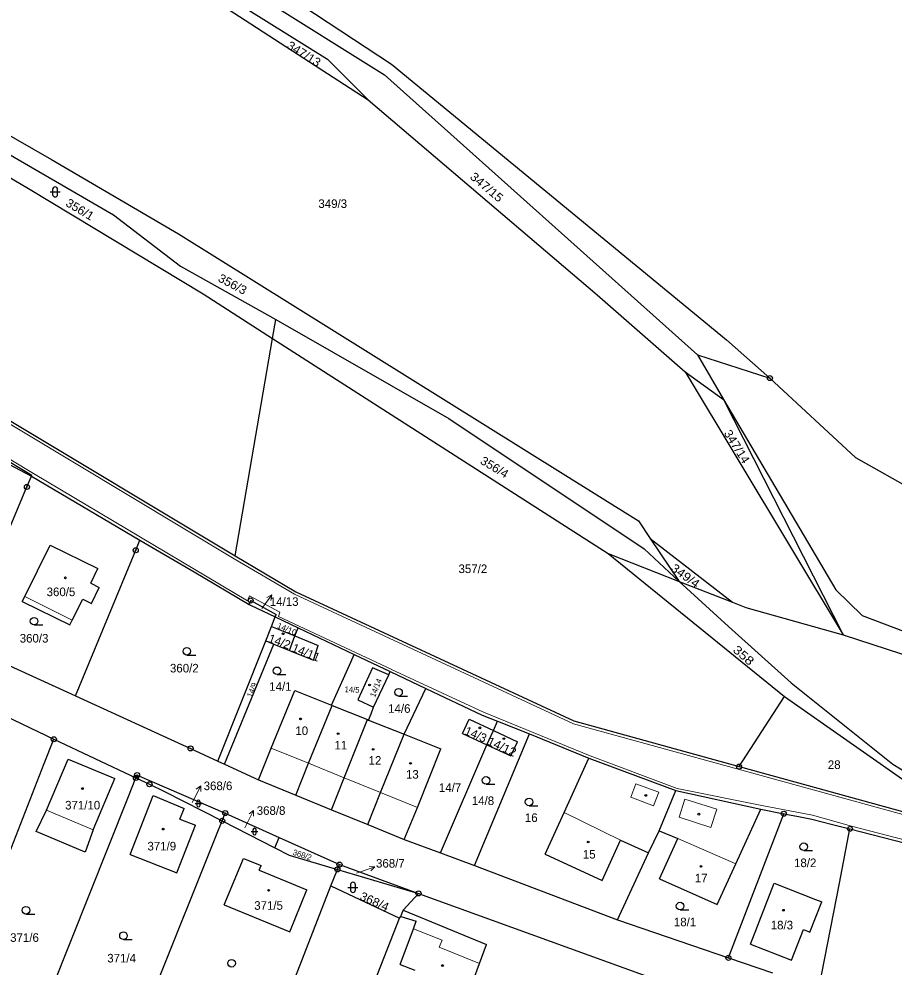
# Model space of a CAD drawing. Extents: x -633485 to -630509, y -1112692 to -1108818.
# Drawn here: x -632263.7 to -632090.4, y -1111838.6 to -1111650.8 of the extents above; entities that cross this region are included whole.
import ezdxf
from ezdxf.enums import TextEntityAlignment as Align

# ---------------------------------------------------------------- set-up
doc = ezdxf.new("R2010")
doc.units = 0
doc.header["$LTSCALE"] = 0.68
for name, color, linetype, lineweight in [('1', 7, 'Continuous', 25), ('3', 7, 'Continuous', 25), ('4', 7, 'Continuous', 13), ('5', 7, 'Continuous', 25), ('7', 7, 'Continuous', 13), ('8', 7, 'Continuous', 25)]:
    doc.layers.add(name, color=color, linetype=linetype, lineweight=lineweight)
doc.layers.add('2', color=7, linetype='Continuous')

msp = doc.modelspace()

# ---------------------------------------------------------------- linework, layer by layer
at = {"layer": '1'}
for p, q in [((-632259.96, -1111613.75), (-632189.94, -1111659.79)), ((-632258.45, -1111619.96), (-632191.31, -1111661.88)), ((-632261.9, -1111621.78), (-632202.65, -1111658.82)), ((-632261.22, -1111623.63), (-632194.6, -1111666.89)), ((-632326.93, -1111645.87), (-632261.86, -1111684.44)), ((-632296.31, -1111656.36), (-632257.3, -1111678.64)), ((-632202.65, -1111658.82), (-632194.6, -1111666.89)), ((-632189.94, -1111659.79), (-632123.57, -1111714.39)), ((-632293.52, -1111661.47), (-632245.01, -1111689.64)), ((-632191.31, -1111661.88), (-632129.37, -1111717.35)), ((-632194.6, -1111666.89), (-632149.21, -1111705.45)), ((-632257.3, -1111678.64), (-632232.16, -1111693.36)), ((-632261.86, -1111684.44), (-632227.27, -1111705.26)), ((-632245.01, -1111689.64), (-632231.75, -1111699.8)), ((-632325.73, -1111694.38), (-632220.93, -1111757.12)), ((-632232.16, -1111693.36), (-632141.06, -1111750.24)), ((-632231.75, -1111699.8), (-632212.85, -1111710.33)), ((-632227.27, -1111705.26), (-632213.5, -1111714.09)), ((-632149.21, -1111705.45), (-632131.81, -1111720.71)), ((-632213.5, -1111714.09), (-632212.85, -1111710.33)), ((-632212.85, -1111710.33), (-632178.58, -1111729.95)), ((-632220.93, -1111757.12), (-632213.5, -1111714.09)), ((-632213.5, -1111714.09), (-632147.05, -1111756.7)), ((-632123.57, -1111714.39), (-632115, -1111721.96)), ((-632129.37, -1111717.35), (-632115, -1111721.96)), ((-632129.37, -1111717.35), (-632124.17, -1111726.18)), ((-632131.81, -1111720.71), (-632124.17, -1111726.18)), ((-632131.81, -1111720.71), (-632100.47, -1111772.77)), ((-632115, -1111721.96), (-632098.05, -1111737.68)), ((-632124.17, -1111726.18), (-632100.47, -1111772.77)), ((-632124.17, -1111726.18), (-632101.97, -1111763.89)), ((-632288.65, -1111726.87), (-632261.27, -1111741.38)), ((-632178.58, -1111729.95), (-632139.91, -1111755.75)), ((-632274.31, -1111733.41), (-632261.17, -1111741.15)), ((-632098.05, -1111737.68), (-632078.38, -1111748.73)), ((-632262.16, -1111743.5), (-632261.27, -1111741.38)), ((-632261.27, -1111741.38), (-632261.17, -1111741.15)), ((-632261.27, -1111741.38), (-632239.78, -1111754.03)), ((-632275.15, -1111774.29), (-632262.16, -1111743.5)), ((-632141.06, -1111750.24), (-632138.7, -1111753.74)), ((-632240.61, -1111756.04), (-632239.78, -1111754.03)), ((-632239.78, -1111754.03), (-632229.03, -1111760.31)), ((-632138.7, -1111753.74), (-632122.42, -1111766.32)), ((-632138.7, -1111753.74), (-632132.97, -1111762.22)), ((-632262.61, -1111765.21), (-632257.55, -1111755)), ((-632257.55, -1111755), (-632248.1, -1111759.68)), ((-632252.52, -1111784.87), (-632240.61, -1111756.04)), ((-632139.91, -1111755.75), (-632132.97, -1111762.22)), ((-632220.93, -1111757.12), (-632208.93, -1111764.3)), ((-632147.05, -1111756.7), (-632112.13, -1111784.99)), ((-632147.05, -1111756.7), (-632132.97, -1111762.22)), ((-632249.53, -1111762.57), (-632248.1, -1111759.68)), ((-632229.03, -1111760.31), (-632218.16, -1111766.76)), ((-632249.53, -1111762.57), (-632247.84, -1111763.4)), ((-632249.39, -1111766.58), (-632247.84, -1111763.4)), ((-632132.97, -1111762.22), (-632123.19, -1111771.16)), ((-632132.97, -1111762.22), (-632122.42, -1111766.32)), ((-632101.97, -1111763.89), (-632096.75, -1111768.94)), ((-632263.08, -1111766.16), (-632262.61, -1111765.21)), ((-632253.18, -1111769.89), (-632251.1, -1111765.73)), ((-632251.1, -1111765.73), (-632249.39, -1111766.58)), ((-632208.93, -1111764.3), (-632153.83, -1111789.82)), ((-632263.08, -1111766.16), (-632253.64, -1111770.81)), ((-632218.16, -1111766.76), (-632217.85, -1111765.99)), ((-632218.16, -1111766.76), (-632217.86, -1111766.94)), ((-632217.86, -1111766.94), (-632212.98, -1111769.25)), ((-632217.85, -1111765.99), (-632212.78, -1111768.74)), ((-632122.42, -1111766.32), (-632119.76, -1111767.35)), ((-632119.76, -1111767.35), (-632100.47, -1111772.77)), ((-632213.72, -1111771.11), (-632212.98, -1111769.25)), ((-632212.98, -1111769.25), (-632212.78, -1111768.74)), ((-632212.98, -1111769.25), (-632208.44, -1111771.4)), ((-632096.75, -1111768.94), (-632068.27, -1111779.85)), ((-632253.64, -1111770.81), (-632253.18, -1111769.89)), ((-632214.87, -1111773.99), (-632213.72, -1111771.11)), ((-632213.72, -1111771.11), (-632209.1, -1111773.01)), ((-632209.1, -1111773.01), (-632208.44, -1111771.4)), ((-632208.44, -1111771.4), (-632197.32, -1111776.68)), ((-632123.19, -1111771.16), (-632110.8, -1111782.31)), ((-632210.14, -1111775.88), (-632209.1, -1111773.01)), ((-632209.1, -1111773.01), (-632204.47, -1111774.91)), ((-632100.47, -1111772.77), (-632053.61, -1111788.03)), ((-632275.23, -1111774.49), (-632252.52, -1111784.87)), ((-632224.35, -1111797.78), (-632214.87, -1111773.99)), ((-632223.06, -1111798.38), (-632213.28, -1111774.62)), ((-632214.87, -1111773.99), (-632213.28, -1111774.62)), ((-632213.28, -1111774.62), (-632210.14, -1111775.88)), ((-632205.4, -1111777.77), (-632204.47, -1111774.91)), ((-632210.14, -1111775.88), (-632205.4, -1111777.77)), ((-632198.01, -1111778.2), (-632197.32, -1111776.68)), ((-632197.32, -1111776.68), (-632190.2, -1111780.05)), ((-632201.87, -1111786.7), (-632198.01, -1111778.2)), ((-632193.75, -1111779.3), (-632196.63, -1111785.65)), ((-632190.51, -1111780.71), (-632193.75, -1111779.3)), ((-632193.55, -1111787.13), (-632190.51, -1111780.71)), ((-632190.51, -1111780.71), (-632190.2, -1111780.05)), ((-632190.2, -1111780.05), (-632183.18, -1111783.39)), ((-632279.29, -1111782.74), (-632256.84, -1111793.46)), ((-632110.8, -1111782.31), (-632090.65, -1111798.4)), ((-632213.82, -1111795.21), (-632209.12, -1111783.8)), ((-632209.12, -1111783.8), (-632201.87, -1111786.7)), ((-632187.47, -1111792.47), (-632183.18, -1111783.39)), ((-632183.18, -1111783.39), (-632172, -1111788.69)), ((-632252.52, -1111784.87), (-632229.74, -1111795.28)), ((-632196.63, -1111785.65), (-632193.55, -1111787.13)), ((-632121.12, -1111798.87), (-632112.13, -1111784.99)), ((-632112.13, -1111784.99), (-632073.84, -1111811.83)), ((-632206.38, -1111798.22), (-632201.7, -1111786.77)), ((-632201.87, -1111786.7), (-632201.7, -1111786.77)), ((-632201.7, -1111786.77), (-632194.68, -1111789.58)), ((-632194.5, -1111789.65), (-632193.99, -1111788.4)), ((-632193.99, -1111788.4), (-632193.55, -1111787.13)), ((-632199.34, -1111801.07), (-632194.68, -1111789.58)), ((-632194.68, -1111789.58), (-632194.5, -1111789.65)), ((-632194.5, -1111789.65), (-632187.47, -1111792.47)), ((-632175.86, -1111792.33), (-632174.55, -1111789.5)), ((-632174.55, -1111789.5), (-632169.78, -1111791.72)), ((-632172, -1111788.69), (-632168.93, -1111789.89)), ((-632169.78, -1111791.72), (-632168.93, -1111789.89)), ((-632168.93, -1111789.89), (-632162.6, -1111792.36)), ((-632153.83, -1111789.82), (-632121.12, -1111798.87)), ((-632171.09, -1111794.54), (-632169.78, -1111791.72)), ((-632169.78, -1111791.72), (-632165.01, -1111793.95)), ((-632258.76, -1111798.26), (-632256.84, -1111793.46)), ((-632256.84, -1111793.46), (-632240.57, -1111801.11)), ((-632192.11, -1111803.99), (-632187.47, -1111792.47)), ((-632187.47, -1111792.47), (-632180.19, -1111795.38)), ((-632175.86, -1111792.33), (-632171.09, -1111794.54)), ((-632173.54, -1111818.43), (-632162.6, -1111792.36)), ((-632166.32, -1111796.76), (-632165.01, -1111793.95)), ((-632162.6, -1111792.36), (-632150.88, -1111797.21)), ((-632229.74, -1111795.28), (-632224.35, -1111797.78)), ((-632216.3, -1111801.52), (-632213.82, -1111795.21)), ((-632184.82, -1111806.94), (-632180.19, -1111795.38)), ((-632180.26, -1111815.96), (-632171.09, -1111794.54)), ((-632171.09, -1111794.54), (-632166.32, -1111796.76)), ((-632258.27, -1111807.53), (-632253.99, -1111797.37)), ((-632253.99, -1111797.37), (-632244.76, -1111801.22)), ((-632224.35, -1111797.78), (-632223.06, -1111798.38)), ((-632155.77, -1111807.99), (-632150.88, -1111797.21)), ((-632150.88, -1111797.21), (-632133.61, -1111803.63)), ((-632283.16, -1111860.74), (-632258.76, -1111798.26)), ((-632223.06, -1111798.38), (-632216.3, -1111801.52)), ((-632208.88, -1111804.55), (-632206.38, -1111798.22)), ((-632121.12, -1111798.87), (-632073.84, -1111811.83)), ((-632090.65, -1111798.4), (-632083.46, -1111802.85)), ((-632249.03, -1111811.42), (-632244.76, -1111801.22)), ((-632242.18, -1111805.12), (-632240.57, -1111801.11)), ((-632240.57, -1111801.11), (-632240.35, -1111800.56)), ((-632240.57, -1111801.11), (-632237.89, -1111802.38)), ((-632240.35, -1111800.56), (-632222.88, -1111808.08)), ((-632216.3, -1111801.52), (-632208.88, -1111804.55)), ((-632201.86, -1111807.42), (-632199.34, -1111801.07)), ((-632237.89, -1111802.38), (-632234.91, -1111803.78)), ((-632264.78, -1111861.71), (-632242.18, -1111805.12)), ((-632241.69, -1111816.26), (-632237.13, -1111804.6)), ((-632237.13, -1111804.6), (-632231.03, -1111807.2)), ((-632234.91, -1111803.78), (-632223.49, -1111809.61)), ((-632208.88, -1111804.55), (-632201.86, -1111807.42)), ((-632194.66, -1111810.37), (-632192.11, -1111803.99)), ((-632136.94, -1111811.57), (-632133.61, -1111803.63)), ((-632133.61, -1111803.63), (-632116.83, -1111807.3)), ((-632187.42, -1111813.33), (-632184.82, -1111806.94)), ((-632260.32, -1111811.75), (-632258.27, -1111807.53)), ((-632231.87, -1111809.27), (-632231.03, -1111807.2)), ((-632223.49, -1111809.61), (-632222.88, -1111808.08)), ((-632222.88, -1111808.08), (-632212.18, -1111812.9)), ((-632201.86, -1111807.42), (-632194.66, -1111810.37)), ((-632159.55, -1111816.18), (-632155.77, -1111807.99)), ((-632122.95, -1111836.03), (-632112.25, -1111808.2)), ((-632121.78, -1111818.14), (-632116.83, -1111807.3)), ((-632116.83, -1111807.3), (-632112.25, -1111808.2)), ((-632112.25, -1111808.2), (-632109.65, -1111808.66)), ((-632109.65, -1111808.66), (-632106.72, -1111809.28)), ((-632232.46, -1111819.89), (-632228.76, -1111810.48)), ((-632231.87, -1111809.27), (-632228.76, -1111810.48)), ((-632224.61, -1111812.39), (-632223.49, -1111809.61)), ((-632223.49, -1111809.61), (-632213.05, -1111814.95)), ((-632194.66, -1111810.37), (-632187.42, -1111813.33)), ((-632106.72, -1111809.28), (-632102.61, -1111810.33)), ((-632102.61, -1111810.33), (-632099.14, -1111811.2)), ((-632244.86, -1111862.76), (-632224.61, -1111812.39)), ((-632139.04, -1111815.92), (-632136.94, -1111811.57)), ((-632136.94, -1111811.57), (-632133.22, -1111813.13)), ((-632101.24, -1111821.96), (-632099.14, -1111811.2)), ((-632099.14, -1111811.2), (-632071.85, -1111818.23)), ((-632213.05, -1111814.95), (-632212.18, -1111812.9)), ((-632212.18, -1111812.9), (-632200.26, -1111818.27)), ((-632187.42, -1111813.33), (-632180.26, -1111815.96)), ((-632148.21, -1111821.42), (-632144.59, -1111813.45)), ((-632144.59, -1111813.45), (-632139.04, -1111815.92)), ((-632136.88, -1111821.08), (-632133.22, -1111813.13)), ((-632241.69, -1111816.26), (-632232.46, -1111819.89)), ((-632213.05, -1111814.95), (-632210.23, -1111816.39)), ((-632210.23, -1111816.39), (-632200.67, -1111819.22)), ((-632180.26, -1111815.96), (-632173.54, -1111818.43)), ((-632159.55, -1111816.18), (-632148.21, -1111821.42)), ((-632145.21, -1111829.21), (-632139.04, -1111815.92)), ((-632223.12, -1111826.27), (-632219.26, -1111817.05)), ((-632219.26, -1111817.05), (-632215.75, -1111818.48)), ((-632200.67, -1111819.22), (-632200.26, -1111818.27)), ((-632200.26, -1111818.27), (-632184.61, -1111823.98)), ((-632173.54, -1111818.43), (-632145.21, -1111829.21)), ((-632125.43, -1111826.15), (-632121.78, -1111818.14)), ((-632216.17, -1111819.38), (-632215.75, -1111818.48)), ((-632216.17, -1111819.38), (-632206.7, -1111823.25)), ((-632201.95, -1111822.48), (-632200.67, -1111819.22)), ((-632200.67, -1111819.22), (-632184.61, -1111823.98)), ((-632136.88, -1111821.08), (-632125.43, -1111826.15)), ((-632118.86, -1111834.05), (-632114.19, -1111821.98)), ((-632114.19, -1111821.98), (-632106, -1111825.17)), ((-632105.33, -1111843.03), (-632101.24, -1111821.96)), ((-632217.08, -1111861.1), (-632201.95, -1111822.48)), ((-632210.12, -1111831.6), (-632206.7, -1111823.25)), ((-632201.95, -1111822.48), (-632188.36, -1111828.9)), ((-632187.62, -1111827.29), (-632184.61, -1111823.98)), ((-632184.61, -1111823.98), (-632129.27, -1111844)), ((-632107.07, -1111831.65), (-632104.74, -1111825.67)), ((-632106, -1111825.17), (-632104.74, -1111825.67)), ((-632223.12, -1111826.27), (-632210.12, -1111831.6)), ((-632188.11, -1111828.54), (-632187.62, -1111827.29)), ((-632187.62, -1111827.29), (-632171.17, -1111834.07)), ((-632198.55, -1111854.72), (-632188.36, -1111828.9)), ((-632188.36, -1111828.9), (-632188.11, -1111828.54)), ((-632188.11, -1111828.54), (-632185.1, -1111829.5)), ((-632185.59, -1111830.98), (-632185.1, -1111829.5)), ((-632145.21, -1111829.21), (-632123.23, -1111836.74)), ((-632188.27, -1111838.03), (-632185.59, -1111830.98)), ((-632110.72, -1111837.19), (-632108.36, -1111831.15)), ((-632108.36, -1111831.15), (-632107.07, -1111831.65)), ((-632172.54, -1111837.85), (-632171.17, -1111834.07)), ((-632118.86, -1111834.05), (-632110.72, -1111837.19)), ((-632123.23, -1111836.74), (-632122.95, -1111836.03)), ((-632123.23, -1111836.74), (-632114.46, -1111839.74)), ((-632188.27, -1111838.03), (-632185.32, -1111839.15)), ((-632175.75, -1111846.71), (-632172.54, -1111837.85))]:
    msp.add_line(p, q, dxfattribs=at)
msp.add_lwpolyline([(-632249.03, -1111811.42), (-632250.62, -1111815.82), (-632260.32, -1111811.75)], dxfattribs=at)
at = {"layer": '3'}
for p, q in [((-632257.581, -1111685.091), (-632255.579, -1111685.091)), ((-632257.081, -1111684.591), (-632257.081, -1111685.592)), ((-632256.079, -1111685.592), (-632256.079, -1111684.591)), ((-632260.753, -1111770.83), (-632259.003, -1111770.83)), ((-632230.493, -1111776.78), (-632228.743, -1111776.78)), ((-632212.623, -1111780.66), (-632210.873, -1111780.66)), ((-632188.563, -1111784.9), (-632186.813, -1111784.9)), ((-632171.223, -1111802.35), (-632169.473, -1111802.35)), ((-632228.861, -1111806.191), (-632227.519, -1111806.191)), ((-632228.525, -1111805.855), (-632228.525, -1111806.526)), ((-632227.855, -1111806.526), (-632227.855, -1111805.855)), ((-632162.713, -1111806.63), (-632160.963, -1111806.63)), ((-632217.741, -1111811.741), (-632216.399, -1111811.741)), ((-632217.405, -1111811.405), (-632217.405, -1111812.076)), ((-632216.735, -1111812.076), (-632216.735, -1111811.405)), ((-632108.313, -1111815.5), (-632106.563, -1111815.5)), ((-632198.601, -1111822.781), (-632196.599, -1111822.781)), ((-632198.101, -1111822.281), (-632198.101, -1111823.282)), ((-632197.099, -1111823.282), (-632197.099, -1111822.281)), ((-632132.793, -1111827.24), (-632131.043, -1111827.24)), ((-632262.353, -1111828.08), (-632260.603, -1111828.08)), ((-632243.043, -1111833.1), (-632241.293, -1111833.1))]:
    msp.add_line(p, q, dxfattribs=at)
for centre in [(-632260.7529, -1111770.0798), (-632230.4929, -1111776.0298), (-632212.6229, -1111779.9098), (-632188.5629, -1111784.1498), (-632171.2229, -1111801.5998), (-632162.7129, -1111805.8798), (-632108.3129, -1111814.7498), (-632132.7929, -1111826.4898), (-632262.3529, -1111827.3298), (-632243.0429, -1111832.3498), (-632221.6229, -1111837.8098)]:
    msp.add_circle(centre, 0.75, dxfattribs=at)
for centre, radius, start, end in [((-632256.58, -1111684.5909), 0.5, 0, 180), ((-632256.58, -1111685.5909), 0.5, 180, 359.98789), ((-632228.19, -1111805.8556), 0.335, 0, 180), ((-632228.19, -1111806.5256), 0.335, 180, 359.98789), ((-632217.07, -1111811.4056), 0.335, 0, 180), ((-632217.07, -1111812.0756), 0.335, 180, 359.98789), ((-632197.6, -1111822.2809), 0.5, 0, 180), ((-632197.6, -1111823.2809), 0.5, 180, 359.98789)]:
    msp.add_arc(centre, radius, start, end, dxfattribs=at)
at = {"layer": '4'}
for p, q in [((-632262.61, -1111765.21), (-632253.18, -1111769.89)), ((-632213.82, -1111795.21), (-632206.38, -1111798.22)), ((-632206.38, -1111798.22), (-632199.34, -1111801.07)), ((-632199.34, -1111801.07), (-632192.11, -1111803.99)), ((-632142.55, -1111804.94), (-632141.56, -1111802.26)), ((-632141.56, -1111802.26), (-632137.03, -1111803.94)), ((-632192.11, -1111803.99), (-632184.82, -1111806.94)), ((-632142.55, -1111804.94), (-632138.04, -1111806.62)), ((-632138.04, -1111806.62), (-632137.03, -1111803.94)), ((-632132.96, -1111808.88), (-632131.88, -1111805.34)), ((-632131.88, -1111805.34), (-632125.54, -1111807.31)), ((-632249.03, -1111811.42), (-632258.27, -1111807.53)), ((-632155.77, -1111807.99), (-632144.59, -1111813.45)), ((-632132.96, -1111808.88), (-632126.72, -1111810.92)), ((-632126.72, -1111810.92), (-632125.54, -1111807.31)), ((-632133.22, -1111813.13), (-632121.78, -1111818.14)), ((-632185.59, -1111830.98), (-632179.95, -1111833.27)), ((-632180.49, -1111834.62), (-632179.95, -1111833.27)), ((-632180.49, -1111834.62), (-632172.54, -1111837.85))]:
    msp.add_line(p, q, dxfattribs=at)
for points in [[(-632121.32, -1111799.36), (-632153.88, -1111790.41), (-632209.17, -1111764.74), (-632221.14, -1111757.71), (-632325.85, -1111694.81), (-632333.76, -1111689.52), (-632341.95, -1111683.42)], [(-632299.24, -1111719.8), (-632274.04, -1111732.92), (-632260.85, -1111740.83), (-632218.48, -1111766.08), (-632218.07, -1111765.09), (-632212.08, -1111768.29), (-632212.31, -1111769.16), (-632189.88, -1111779.63)], [(-632189.94, -1111779.63), (-632171.73, -1111788.1), (-632150.63, -1111796.76), (-632133.35, -1111803.2), (-632116.61, -1111806.57), (-632106.56, -1111808.49), (-632098.83, -1111810.64), (-632072.34, -1111817.55), (-632072.75, -1111816.1), (-632062.98, -1111814.99), (-632051.99, -1111812.26), (-632052.29, -1111810.51)], [(-632052.29, -1111810.51), (-632036.9, -1111809.18), (-632037.48, -1111804), (-632062.36, -1111810.51), (-632070.38, -1111811.56), (-632073.81, -1111812.43), (-632121.32, -1111799.36)]]:
    msp.add_lwpolyline(points, dxfattribs=at)
at = {"layer": '5'}
for centre in [(-632254.5568, -1111761.4992), (-632211.4168, -1111772.5692), (-632194.2935, -1111782.7159), (-632207.9568, -1111789.4392), (-632172.4468, -1111791.1892), (-632200.5368, -1111792.3592), (-632167.6868, -1111793.3392), (-632193.6068, -1111795.4592), (-632186.1968, -1111798.2292), (-632251.1768, -1111803.2292), (-632139.5868, -1111804.5792), (-632129.0868, -1111808.2992), (-632235.1668, -1111811.2392), (-632150.9868, -1111813.7992), (-632128.6468, -1111818.6292), (-632214.2868, -1111823.3692), (-632112.3268, -1111827.3192), (-632179.8468, -1111838.2792)]:
    msp.add_circle(centre, 0.175, dxfattribs=at)
at = {"layer": '7'}
for p, q in [((-632213.676, -1111764.882), (-632214.67, -1111765.398)), ((-632227.718, -1111802.686), (-632228.618, -1111803.351)), ((-632217.278, -1111807.546), (-632218.178, -1111808.211)), ((-632193.283, -1111818.713), (-632194.392, -1111818.566))]:
    msp.add_line(p, q, dxfattribs=at)
for points in [[(-632215.63, -1111767.57), (-632215.44, -1111767.31), (-632213.676, -1111764.882), (-632213.86, -1111765.987)], [(-632229.41, -1111806), (-632229.08, -1111805.36), (-632227.718, -1111802.686), (-632227.726, -1111803.806)], [(-632219.02, -1111810.98), (-632218.64, -1111810.22), (-632217.278, -1111807.546), (-632217.286, -1111808.666)], [(-632196.9, -1111819.97), (-632196.12, -1111819.69), (-632193.283, -1111818.713), (-632194.066, -1111819.512)]]:
    msp.add_lwpolyline(points, dxfattribs=at)
at = {"layer": '8'}
for centre, radius in [((-632115, -1111721.9599), 0.5), ((-632115, -1111721.9599), 0.0303), ((-632262.16, -1111743.4999), 0.5), ((-632262.16, -1111743.4999), 0.0303), ((-632240.61, -1111756.0399), 0.5), ((-632240.61, -1111756.0399), 0.0303), ((-632217.85, -1111765.9899), 0.5), ((-632217.85, -1111765.9899), 0.0303), ((-632256.84, -1111793.4599), 0.5), ((-632256.84, -1111793.4599), 0.0303), ((-632229.74, -1111795.2799), 0.5), ((-632229.74, -1111795.2799), 0.0303), ((-632121.12, -1111798.8699), 0.5), ((-632121.12, -1111798.8699), 0.0303), ((-632240.57, -1111801.1099), 0.5), ((-632240.35, -1111800.5599), 0.5), ((-632240.57, -1111801.1099), 0.0303), ((-632240.35, -1111800.5599), 0.0303), ((-632237.89, -1111802.3799), 0.5), ((-632237.89, -1111802.3799), 0.0303), ((-632222.88, -1111808.0799), 0.5), ((-632222.88, -1111808.0799), 0.0303), ((-632112.25, -1111808.1999), 0.5), ((-632112.25, -1111808.1999), 0.0303), ((-632223.49, -1111809.6099), 0.5), ((-632223.49, -1111809.6099), 0.0303), ((-632099.14, -1111811.1999), 0.5), ((-632099.14, -1111811.1999), 0.0303), ((-632200.26, -1111818.2699), 0.5), ((-632200.26, -1111818.2699), 0.0303), ((-632200.67, -1111819.2199), 0.5), ((-632200.67, -1111819.2199), 0.0303), ((-632184.61, -1111823.9799), 0.5), ((-632184.61, -1111823.9799), 0.0303), ((-632123.23, -1111836.7399), 0.5), ((-632123.23, -1111836.7399), 0.0303)]:
    msp.add_circle(centre, radius, dxfattribs=at)

# ---------------------------------------------------------------- texts
at = {"layer": '2'}
for s, height, rotation, width, p in [('347/13', 1.7, 328, 1.05, (-632210.835, -1111656.54)), ('347/15', 1.7, 320, 1.1, (-632174.563, -1111682.335)), ('356/1', 1.7, 329, 1.05, (-632254.658, -1111687.744)), ('356/3', 1.7, 332, 1.05, (-632224.469, -1111702.695)), ('347/14', 1.7, 302, 1.05, (-632124.2, -1111732.865)), ('356/4', 1.7, 329, 1.05, (-632172.548, -1111738.784)), ('349/4', 1.7, 324, 1.1, (-632134.769, -1111759.943)), ('14/10', 1.139, 337, 1.05, (-632212.751, -1111771.382)), ('358', 1.7, 319, 1.2, (-632122.488, -1111776)), ('368/4', 1.7, 336, 1.05, (-632196.392, -1111825.148))]:
    msp.add_text(s, height=height, rotation=rotation, dxfattribs=dict(at, width=width)).set_placement(p)
for s, p in [('349/3', (-632204.44, -1111688.265)), ('357/2', (-632176.68, -1111760.555)), ('360/5', (-632258.27, -1111765.125)), ('360/3', (-632263.6, -1111774.315)), ('360/2', (-632233.84, -1111780.235)), ('14/1', (-632214.17, -1111783.865)), ('14/6', (-632190.62, -1111788.225)), ('10', (-632209, -1111792.625)), ('11', (-632201.26, -1111795.475)), ('12', (-632194.5, -1111798.495)), ('28', (-632103.53, -1111799.345)), ('13', (-632187.09, -1111801.265)), ('14/7', (-632180.57, -1111803.875)), ('14/8', (-632174.05, -1111806.485)), ('371/10', (-632254.61, -1111807.365)), ('16', (-632163.54, -1111809.835)), ('371/9', (-632238.3, -1111815.475)), ('15', (-632152.05, -1111817.075)), ('18/2', (-632110.23, -1111818.775)), ('17', (-632129.89, -1111821.805)), ('371/5', (-632217.15, -1111827.225)), ('18/1', (-632134.02, -1111830.485)), ('18/3', (-632114.84, -1111831.105)), ('371/6', (-632265.49, -1111833.575)), ('371/4', (-632246.26, -1111837.655))]:
    msp.add_text(s, height=1.7, dxfattribs=at).set_placement(p)
for s, p in [('14/13', (-632211.21, -1111767.055)), ('368/6', (-632224.32, -1111803.535)), ('368/8', (-632213.81, -1111808.425)), ('368/7', (-632190.18, -1111818.875))]:
    msp.add_text(s, height=1.7, dxfattribs=at).set_placement(p, align=Align.CENTER)
for s, height, rotation, p in [('14/2', 1.7, 340, (-632214.495, -1111774.169)), ('14/11', 1.7, 338, (-632209.829, -1111776.014)), ('14/9', 1.139, 68, (-632217.595, -1111785.286)), ('14/5', 1.139, 357, (-632199.274, -1111784.124)), ('14/3', 1.7, 337, (-632175.636, -1111792.431))]:
    msp.add_text(s, height=height, rotation=rotation, dxfattribs=at).set_placement(p)
for s, rotation, p in [('14/14', 68, (-632192.5182, -1111783.4923)), ('368/2', 342, (-632207.7985, -1111816.8992))]:
    msp.add_text(s, height=1.139, rotation=rotation, dxfattribs=at).set_placement(p, align=Align.CENTER)
at = {"layer": '2', "width": 1.05}
msp.add_text('14/12', height=1.7, rotation=335, dxfattribs=at).set_placement((-632168.4357, -1111795.7099), align=Align.CENTER)

doc.saveas('drawing.dxf')
